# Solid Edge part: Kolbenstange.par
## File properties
Username: bmolnar
Dokumentum tartalom típus: 0
Author: bmolnar
Last saved by: bmolnar
Revision: 82
Sűrűség: 0,000 kg/m^3
Pontosság: 0,990
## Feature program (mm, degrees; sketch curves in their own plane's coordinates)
base feature "unnamed BaseFeature 1"
sketch for "unnamed Protrusion 1" plane through (49.2, 0, 0) normal (1, 0, 0) x-axis (0, -1, 0)
  circle centre (0, 0) radius 50
extrude "unnamed Protrusion 1" add finite 15.9 along +normal
sketch for "Kihúzás_2" #1 plane through (49.2, 0, 0) normal (1, 0, 0) x-axis (0, -1, 0)
  circle centre (0, 0) radius 12.5
sketch for "Kihúzás_2" #2 plane through (49.2, 0, 0) normal (1, 0, 0) x-axis (0, -1, 0)
  circle centre (0, 0) radius 50
extrude "Kihúzás_2" add finite 28.3 along -normal
sketch for "Furat_1" plane through (-50, 0.0012, 0) normal (-1, 0, 0) x-axis (0, 1, 0)
  hole centre (-0.0012, 0) bore radius 5.053
hole "Furat_1" nominal diameter 12 finite  VBottomAngle = 118 deg; ThreadDepth = 22 mm
chamfer "Letörés_1" setback 1  SetBackValue2 = 45 deg
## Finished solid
Body 1: solid body, 14 faces, 20 edges, 8 vertices.
  Faces by surface: plane 7, cylinder 4, cone 2, torus 1
  Edges by curve: circle 10, line 6, curve on surface 2, ellipse 2
Bounding box of the edges (mm; curved faces can reach further): 115.100 x 100.000 x 100.000, from (-50, -50, -50) to (65.1, 50, 50).
Cylindrical faces by radius (mm): R5.053 x2, R12.5 x1, R50 x1
Conical faces (half-angle, radius in mm at the cone's reference point): 45 deg R6.053 x1, 59 deg R5.053 x1
Toroidal faces (ring radius, tube radius in mm): R10.7 r1.8 x1
Planar faces by outward normal: +x 1, +z 1, -x 2, -z 1, oblique 2
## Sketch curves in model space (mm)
circle centre (49.2, 0, 0) radius 12.5
circle centre (49.2, 0, 0) radius 50
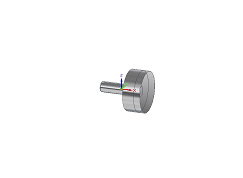
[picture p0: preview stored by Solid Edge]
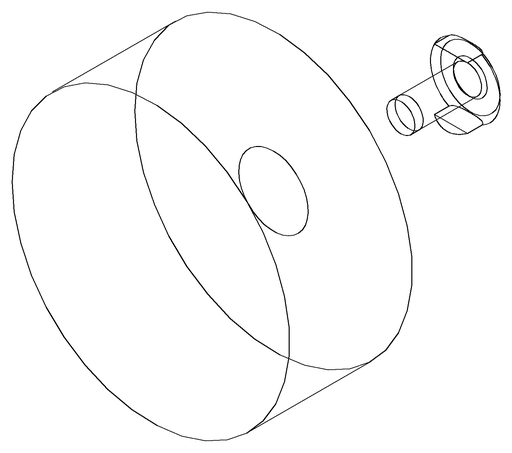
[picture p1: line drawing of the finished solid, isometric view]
